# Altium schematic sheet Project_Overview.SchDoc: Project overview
size A4; Date: Not used; ApprovedBy: Not used; CheckedBy: Not used; Author: Not used; CompanyName: STMicroelectronics; DrawnBy: Not used; Engineer: Not used; Organization: Not used; Address1: Not used; Address2: Not used; Address3: Not used; Address4: Not used; DocumentNumber: Not used; Revision: Not used; SheetNumber: 1; SheetTotal: 9
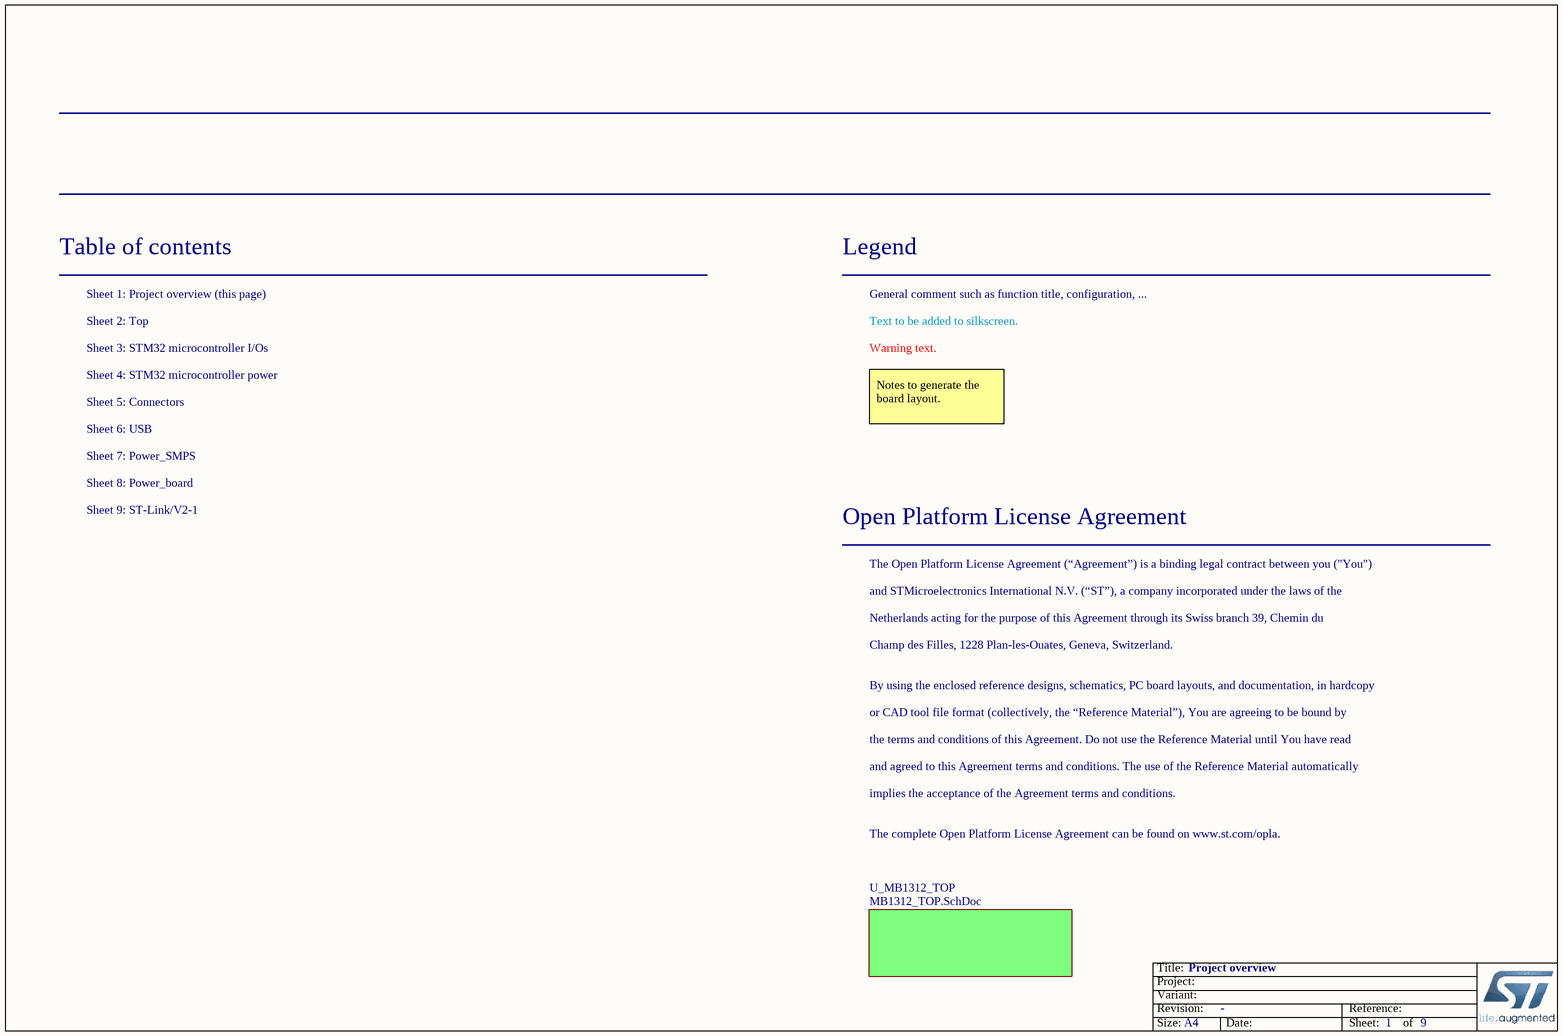
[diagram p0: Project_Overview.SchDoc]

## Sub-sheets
U_MB1312_TOP = MB1312_TOP.SchDoc: no entries

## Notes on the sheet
- Table of contents
- Sheet 1: Project overview (this page)
- Legend
- General comment such as function title, configuration, ...
- Sheet 2: Top
- Sheet 4: STM32 microcontroller power
- Sheet 3: STM32 microcontroller I/Os
- Text to be added to silkscreen.
- Warning text.
- Sheet 6: USB
- Sheet 5: Connectors
- Notes to generate the board layout.
- Sheet 7: Power_SMPS
- Sheet 9: ST-Link/V2-1
- Sheet 8: Power_board
- Open Platform License Agreement
- The Open Platform License Agreement (“Agreement”) is a binding legal contract between you ("You")
- and STMicroelectronics International N.V. (“ST”), a company incorporated under the laws of the
- Netherlands acting for the purpose of this Agreement through its Swiss branch 39, Chemin du
- Champ des Filles, 1228 Plan-les-Ouates, Geneva, Switzerland.
- By using the enclosed reference designs, schematics, PC board layouts, and documentation, in hardcopy
- or CAD tool file format (collectively, the “Reference Material”), You are agreeing to be bound by
- the terms and conditions of this Agreement. Do not use the Reference Material until You have read
- and agreed to this Agreement terms and conditions. The use of the Reference Material automatically
- implies the acceptance of the Agreement terms and conditions.
- The complete Open Platform License Agreement can be found on www.st.com/opla.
